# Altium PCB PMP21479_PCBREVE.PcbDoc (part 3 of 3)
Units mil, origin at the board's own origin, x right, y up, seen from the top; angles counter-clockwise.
Board outline 1915.03 x 2932.53 mil, 4 copper layers (Top Layer, Signal Layer 1, Signal Layer 2, Bottom Layer), stack 39.6 mil thick; 137 components, 82 nets, 411 pads, 91 vias.
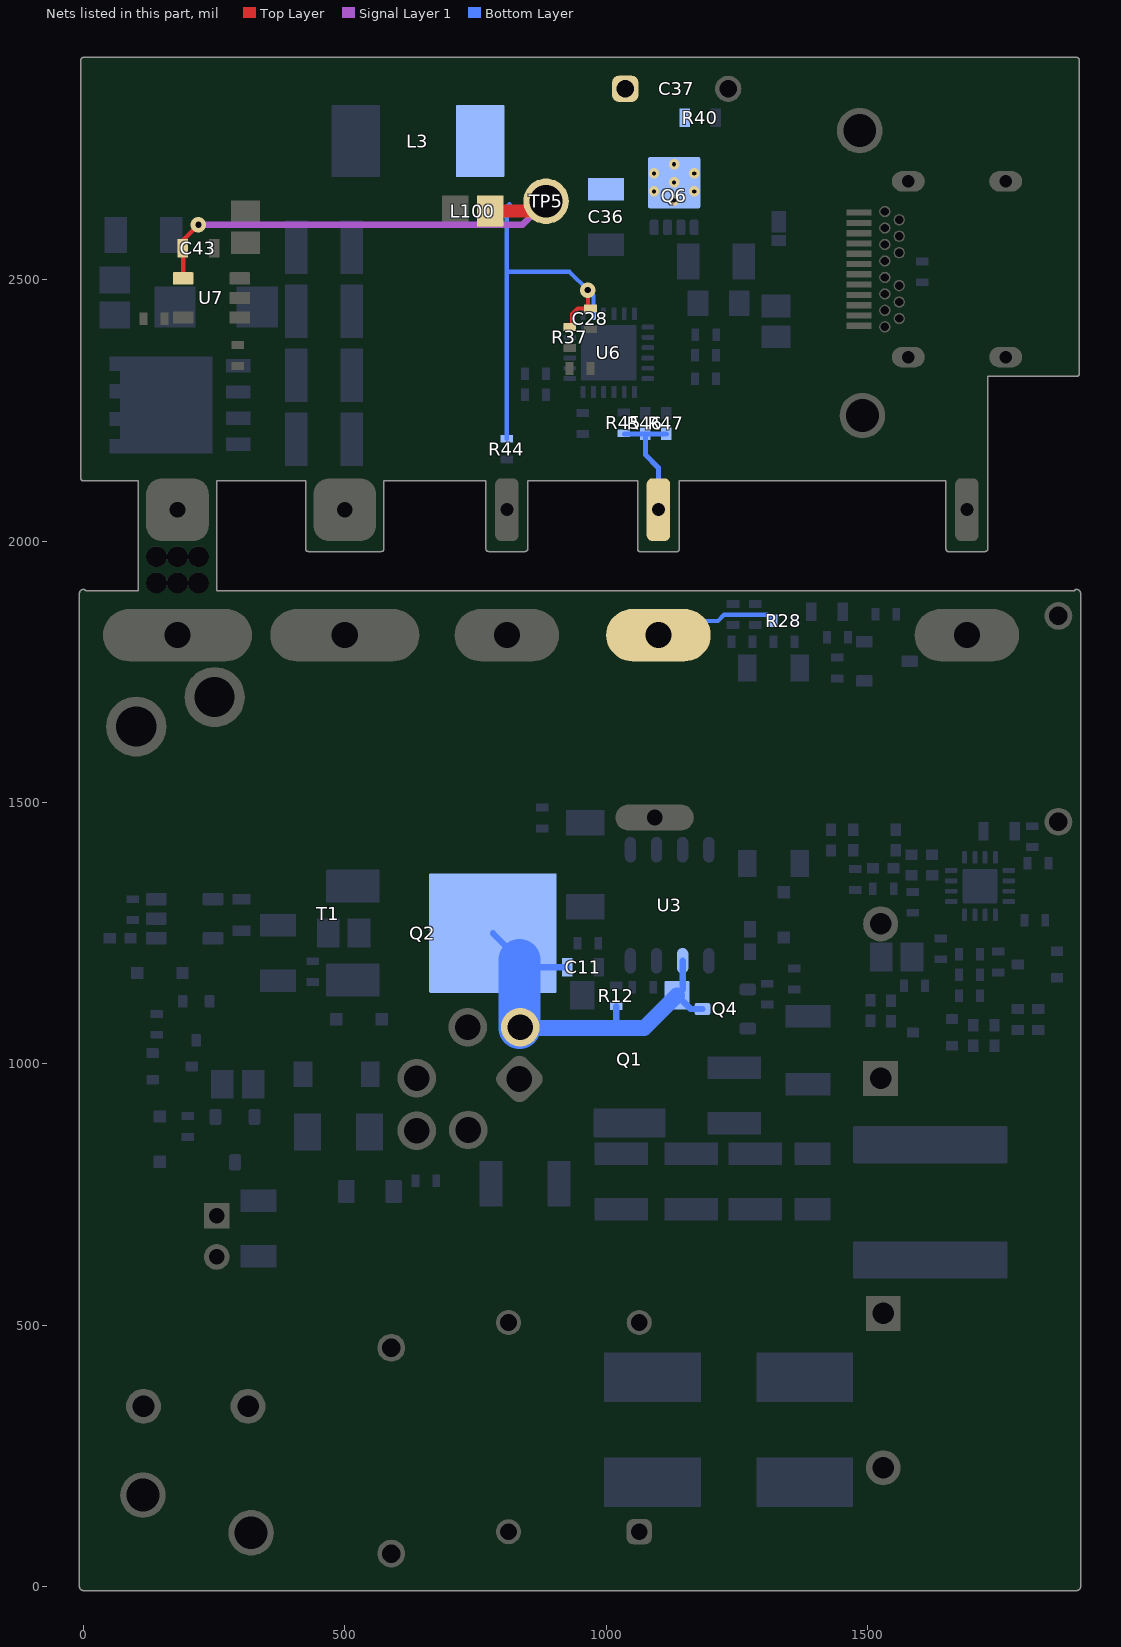
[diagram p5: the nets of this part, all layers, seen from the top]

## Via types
v1: diameter 30, hole 12, Top Layer to Bottom Layer, 44 vias
v2: diameter 30, hole 12, Top Layer to Bottom Layer, tented both sides, 31 vias
v3: diameter 19.68, hole 7.87, Top Layer to Bottom Layer, 11 vias
v4: diameter 30, hole 12, Top Layer to Bottom Layer, tented bottom, 2 vias
v5: diameter 19.68, hole 7.87, Top Layer to Bottom Layer, tented both sides, 1 vias
v6: diameter 30, hole 12, Top Layer to Bottom Layer, tented top, 1 vias
v7: diameter 34, hole 16, Top Layer to Bottom Layer, 1 vias

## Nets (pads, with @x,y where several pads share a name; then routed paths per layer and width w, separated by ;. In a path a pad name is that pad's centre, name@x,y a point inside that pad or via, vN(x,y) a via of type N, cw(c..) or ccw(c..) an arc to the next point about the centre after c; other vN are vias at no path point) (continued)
Vout: C28.1 C36.1 C37.1 C43.1 L3.2 L100.2 Q6.5 Q6.6 Q6.7 Q6.8 Q6.9@1130,2685.59 R37.2 R40.2 R44.1 TP5.1 U6.20 U7.4 | length 1680
  Top Layer w8: C43.1@190,2560 190,2575 v1(220,2605) ; U7.4@190.87,2502.4 C43.1@190.87,2559.13 ; R37.2@930.2,2409.53 935,2414.33 935,2434.41 945.59,2445 C28.1@970,2445 965,2450 v1(965,2480)
  Top Layer w25: L100.2@785,2631.14 866.14,2631.14 TP5.1@885,2650
  Signal Layer 1 w12: v1(220,2605) 840,2605 TP5.1@885,2650
  Bottom Layer w8: R44.1@810,2195 810,2515 ; 815,2645 810,2640 810,2515 ; U6.20@975.47,2434.8 975.47,2469.53 v1(965,2480) 930,2515 810,2515
  other v3: 1130,2651.65 1091.61,2668.9 1168.39,2668.9 1130,2686.14 1091.61,2703.39 1168.39,2703.39
  other v5: 1130,2720.63
VOUT_CTL: pad.2@1100,2060 R45.2 R46.1 R47.1 | length 235.4
  Bottom Layer w10: R45.2@1035,2205 R46.1@1075,2205 ; pad.2@1100,2060 1100,2140 1075,2165 R46.1@1075,2205 ; R47.1@1115,2205 R46.1@1075,2205
VOUT_CTL1: pad.0@1100,1820 R28.1 | length 241.1
  Bottom Layer w8: pad.0@1100,1820 1127.15,1847.15 1213.8,1847.15 1225.67,1859.01 1308.13,1859.01 R28.1@1320,1847.15
Vswn: C11.2 Q1.3 Q2.4 Q4.3 R12.1 T1.2 U3.6 | length 799.4
  Bottom Layer w12: Q2.4@783.36,1250 834.31,1199.05 848.56,1184.79 C11.2@925.79,1184.79 ; R12.1@1019.18,1110 1019.18,1071.68 1022.19,1068.67 ; U3.6@1146.32,1197.06 1146.32,1141.97 Q1.3@1135.55,1131.2 1161.84,1104.92 Q4.3@1184.19,1104.92
  Bottom Layer w30: T1.2@834.31,1068.67 1022.19,1068.67 1073.02,1068.67 Q1.3@1135.55,1131.2
  Bottom Layer w80: T1.2@834.31,1068.67 Q2.4@834.31,1199.05
pads on no net: J1.A2 J1.A3 J1.A8 J1.A10 J1.A11 J1.B2 J1.B3 J1.B8 J1.B10 J1.B11 Q6.9@1091.61,2706.26 Q6.9@1103.92,2651.65 Q6.9@1103.92,2686.14 Q6.9@1117.2,2706.26 Q6.9@1130,2672.89 Q6.9@1142.8,2706.26 Q6.9@1156.08,2651.65 Q6.9@1156.08,2686.14 Q6.9@1168.39,2706.26 T1.3 U2.17@1715,1340 U6.9 U6.10 U6.11 U6.25@977.64,2332.64 U6.25@977.64,2387.36 U6.25@1032.36,2332.64 U6.25@1032.36,2387.36

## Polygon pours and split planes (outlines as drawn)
NetC17_2 on Bottom Layer "BOTTOM_LAYER_NETC17_2_P006" (solid, remove dead copper, pour order 6): 75.26,1329.13 75.26,1227.57 620,1227.57 620,1329.13
Vbulk on Bottom Layer "BOTTOM_LAYER_VBULK_P000" (solid, remove dead copper, pour order 0): 1777.51,900.35 1777.51,680.39 1456.03,680.39 1456.03,900.35
no net on Bottom Layer "BOTTOM_LAYER_NONET_P044" (solid, remove dead copper, pour order 44): 1765.79,950.32
PGND on Bottom Layer "BOTTOM_LAYER_PGND_P018" (solid, remove dead copper, pour order 18): -5.02,1329.13 -5.02,560 375,560 375,1329.13
PGND on Bottom Layer "BOTTOM_LAYER_PGND_P014" (solid, remove dead copper, pour order 14): 1285,1184.09 1285,-5.02 1897.49,-5.02 1897.49,1184.09
PGND on Bottom Layer "BOTTOM_LAYER_PGND_P012" (solid, remove dead copper, pour order 12): 276.42,1470 276.42,680 1905.02,680 1905.02,1470
ICGND on Bottom Layer "BOTTOM_LAYER_ICGND_P010" (solid, remove dead copper, pour order 10): 1550,1470 1550,1017.49 1905.02,1017.49 1905.02,1470
NetC17_2 on Bottom Layer "BOTTOM_LAYER_NETC17_2_P008" (solid, remove dead copper, pour order 8): 365.51,1470.49 365.51,1270.54 1220.12,1270.54 1220.12,1470.49
Vbulk on Bottom Layer "BOTTOM_LAYER_VBULK_P004" (solid, remove dead copper, pour order 4): 1600.54,680.39 880,680.39 880,1015 1600.54,1015
SGND1 on Bottom Layer "BOTTOM_LAYER_SGND1_P022" (solid, remove dead copper, pour order 22): 1260,1900 1260,1721.57 1900,1721.57 1900,1900
VDRN on Bottom Layer "BOTTOM_LAYER_VDRN_P026" (solid, remove dead copper, pour order 26): 25,2465 25,2145 252.52,2145 252.52,2465
VN on Bottom Layer "BOTTOM_LAYER_VN_P030" (solid, remove dead copper, pour order 30): 440.32,2895 440.32,2145 790,2145 790,2895
Vout on Bottom Layer "BOTTOM_LAYER_VOUT_P028" (solid, remove dead copper, pour order 28): 705.41,2895 705.41,2625 1180,2625 1180,2895
NetQ6_1 on Bottom Layer "BOTTOM_LAYER_NETQ6_1_P034" (solid, remove dead copper, pour order 34): 1105,2615 1105,2490 1190,2490 1190,2615
VBUS on Bottom Layer "BOTTOM_LAYER_VBUS_P038" (solid, remove dead copper, pour order 38): 1230,2585 1230,2425 1570,2425 1570,2585
SGND on Bottom Layer "BOTTOM_LAYER_SGND_P040" (solid, remove dead copper, pour order 40): -5.02,2925.02 -5.02,2145 1905.02,2145 1905.02,2925.02
VDRN1 on Bottom Layer "BOTTOM_LAYER_VDRN1_P042" (solid, remove dead copper, pour order 42): 0,1895 0,1570 365,1570 365,1895
PGND on Signal Layer 2 "SIGNAL_LAYER_2_PGND_P102" (solid, remove dead copper, pour order 102): 1905.02,1469.37 515.95,1469.37 328.45,1281.87 328.45,679.37 766.42,679.37 1905.02,679.37
PGND on Signal Layer 2 "SIGNAL_LAYER_2_PGND_P068" (solid, remove dead copper, pour order 68): 0,1328.52 0,560 375,560 375,1328.52
PGND on Signal Layer 2 "SIGNAL_LAYER_2_PGND_P052" (solid, remove dead copper, pour order 52): 1285,870 1285,0 1900,0 1900,870
PGND on Signal Layer 2 "SIGNAL_LAYER_2_PGND_P048" (solid, remove dead copper, pour order 48): 553.79,1470 553.79,680.39 1880,680.39 1880,1470
ICGND on Signal Layer 2 "SIGNAL_LAYER_2_ICGND_P046" (solid, remove dead copper, pour order 46): 1488.13,1468.74 1488.13,1013.66 1900,1013.66 1900,1468.74
SGND1 on Signal Layer 2 "SIGNAL_LAYER_2_SGND1_P070" (solid, remove dead copper, pour order 70): 860,1894.5 860,1720 1900,1720 1900,1894.5
VBUS on Signal Layer 2 "SIGNAL_LAYER_2_VBUS_P078" (solid, remove dead copper, pour order 78): 1285,2865 1285,2425 1555,2425 1555,2865
SGND on Signal Layer 2 "SIGNAL_LAYER_2_SGND_P084" (solid, remove dead copper, pour order 84): 0,2920 0,2145 1900,2145 1900,2920
VDRN1 on Signal Layer 2 "SIGNAL_LAYER_2_VDRN1_P090" (solid, remove dead copper, pour order 90): 2.51,1890 2.51,1570 365,1570 365,1890
PGND on Signal Layer 1 "SIGNAL_LAYER_1_PGND_P100" (solid, remove dead copper, pour order 100): 764.72,1470.2 513.79,1470.2 326.29,1282.69 326.29,680.2 764.26,680.2 764.65,680.59
PGND on Signal Layer 1 "SIGNAL_LAYER_1_PGND_P066" (solid, remove dead copper, pour order 66): 0,1327.19 0,560 1205.94,560 1205.94,1327.19
PGND on Signal Layer 1 "SIGNAL_LAYER_1_PGND_P056" (solid, remove dead copper, pour order 56): 1285,1465 1285,0 1900,0 1900,1465
PGND on Signal Layer 1 "SIGNAL_LAYER_1_PGND_P050" (solid, remove dead copper, pour order 50): 520.5,1470 520.5,680 1880,680 1880,1470
SGND1 on Signal Layer 1 "SIGNAL_LAYER_1_SGND1_P072" (solid, remove dead copper, pour order 72): 860,1894.5 860,1720 1900,1720 1900,1894.5
SGND on Signal Layer 1 "SIGNAL_LAYER_1_SGND_P080" (solid, remove dead copper, pour order 80): 0,2920 0,2145 1900,2145 1900,2920
VN1 on Signal Layer 1 "SIGNAL_LAYER_1_VN1_P092" (solid, remove dead copper, pour order 92): 2.51,1890.46 2.52,1560 700,1560 700,1890.46
PGND on Top Layer "TOP_LAYER_PGND_P096" (solid, remove dead copper, pour order 96): 767.41,1470 516.48,1470 328.98,1282.5 328.98,680 766.95,680 767.34,680.39
PGND on Top Layer "TOP_LAYER_PGND_P064" (solid, remove dead copper, pour order 64): 0,1328.52 0,560 375,560 375,1328.52
PGND on Top Layer "TOP_LAYER_PGND_P062" (solid, remove dead copper, pour order 62): 1285,1470 1285,0 1900,0 1900,1470
PGND on Top Layer "TOP_LAYER_PGND_P058" (solid, remove dead copper, pour order 58): 525.21,1470 525.21,680 1880,680 1880,1470
SGND1 on Top Layer "TOP_LAYER_SGND1_P074" (solid, remove dead copper, pour order 74): 860,1895 860,1720 1900,1720 1900,1895
VBUS on Top Layer "TOP_LAYER_VBUS_P076" (solid, remove dead copper, pour order 76): 1286.9,2585 1286.9,2425 1545,2425 1545,2585
SGND on Top Layer "TOP_LAYER_SGND_P086" (solid, remove dead copper, pour order 86): 0,2920 0,2145 1900,2145 1900,2920
VN1 on Top Layer "TOP_LAYER_VN1_P094" (solid, remove dead copper, pour order 94): 0,1890 0,1565 700,1565 700,1890

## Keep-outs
Keep-Out Layer:
  text ".Layer_Name" at 577,-858.49 h60

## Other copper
Top Layer:
  text ".Layer_Name" at 577,-858.49 h60
Signal Layer 1:
  pour cut-out: 655,1370 655,1115 1005.12,1115 1005.12,1370
  pour cut-out: 803.31,1275 803.31,1040.65 1168.81,1040.65 1168.81,1275
Signal Layer 2:
  pour cut-out: 802.84,1275.2 802.84,1040.65 1169.05,1040.65 1169.05,1275.2
  pour cut-out: 655,1370.01 655,1115 1005,1115 1005,1370.01
Bottom Layer:
  text ".Layer_Name" at 577,-858.49 h60

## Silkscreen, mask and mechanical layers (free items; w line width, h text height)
Top Overlay:
  text "NEUT" at 235,190 h40
  text "LINE" at 40,50 h40
  text ".Layer_Name" at 577,-858.49 h60
Bottom Overlay:
  text "PMP21479PCB-E" at 1870,40 h108.27
  text ".Layer_Name" at 577,-858.49 h60
Top Paste:
  text ".Layer_Name" at 577,-858.49 h60
Bottom Paste:
  text ".Layer_Name" at 577,-858.49 h60
Top Solder:
  text ".Layer_Name" at 577,-858.49 h60
  text ".Layer_Name" at 577,-858.49 h60
Bottom Solder:
  text ".Layer_Name" at 577,-858.49 h60
Drill Guide:
  text ".Layer_Name" at 577,-858.49 h60
M1 Board Outline:
  lines w5: 285,1567.5 ccw(c285,1570) 286.77,1568.23 ; 285,1567.5 ccw(c285,1570) 286.77,1568.23 ; 285,1567.5 27.5,1567.5 27.5,1532.15 299.31,1532.15 418.58,1651.42 ; 286.77,1568.23 406.04,1687.5 997.5,1687.5 997.5,1652.15 420.35,1652.15 ; 400,482.5 ccw(c400,485) 402.5,485 ; 400,482.5 ccw(c400,485) 402.5,485 ; 400,482.5 47.5,482.5 47.5,447.5 437.5,447.5 437.5,620 ; 402.5,485 402.5,657.5 1247.5,657.5 1247.5,622.5 440,622.5 ; 418.58,1651.42 cw(c420.35,1649.65) 420.35,1652.15 ; 418.58,1651.42 cw(c420.35,1649.65) 420.35,1652.15 ; 437.5,620 cw(c440,620) 440,622.5 ; 437.5,620 cw(c440,620) 440,622.5 ; -10.02,0 ccw(c0,0) 0,-10.02 1900,-10.02 ccw(c1900,0) 1910.02,0 1910.02,1900 ccw(c1900,1900) 1900,1910.02 ccw(c1900,1902.5) 1894.4,1907.52 257.52,1907.52 257.52,2112.49 422.48,2112.72 422.48,1985 ccw(c430,1985) 430,1977.48 570,1977.48 ccw(c570,1985) 577.52,1985 577.52,2112.48 767.48,2112.48 767.48,1985 ccw(c775,1985) 775,1977.48 845,1977.48 ccw(c845,1985) 852.52,1985 852.52,2112.48 1057.48,2112.48 1057.48,1984.76 ccw(c1065,1984.76) 1065,1977.24 1135,1977.24 ccw(c1135,1984.76) 1142.52,1984.76 1142.52,2112.72 1647.48,2112.49 1647.48,1984.76 ccw(c1655,1984.76) 1656.9,1977.48 1725,1977.48 ccw(c1725,1985) 1732.52,1985 1732.52,2312.48 1900,2312.48 ccw(c1900,2320) 1907.52,2320 1907.52,2920 ccw(c1900,2920) 1900,2927.52 0,2927.52 ccw(c0,2920) -7.52,2920 -7.52,2120 ccw(c0,2120) 0,2112.48 102.48,2112.48 102.48,1907.52 5.6,1907.52 ccw(c0,1902.5) 0,1910.02 ccw(c0,1900) -10.02,1900 -10.02,0
  text ".Layer_Name" at 577,-858.49 h60
M2 Board Dimensions:
  rectangle: 125,-400 500,-275
  rectangle: 0,-275 125,-150
  lines w7: 0,-275 1000,-275 ; 125,-400 125,-150 ; 250,-400 250,-150 ; 500,-400 500,-150 ; 750,-400 750,-150 ; 0,-400 0,-150 1000,-150 1000,-400 0,-400
  text ".Layer_Name" at 577,-858.49 h60
M3 3D STEP Top:
  text ".Layer_Name" at 577,-858.49 h60
M4 3D STEP Bottom:
  text ".Layer_Name" at 577,-858.49 h60
M5 Assembly Top:
  lines w10: -292,-930.17 6308,-930.17 ; -292,-726.83 6310,-726.83 ; -292,-523.5 -292,-1133.5 3713,-1133.5 6310,-1133.5 6310,-523.5 -291.5,-523.5 -291.5,-1133.5 1284,-1133.5 ; 2173,-1133.5 2173,-523.5 ; 3440,-726.83 3440,-523.5 ; 4280,-726.83 4280,-523.5 ; 4902,-1140 4902,-937.17
  text "COMPONENTS MARKED 'DNP' SHOULD NOT BE POPULATED." at 1153.5,-318.5 h60
  text "ASSEMBLY VARIANT:" at 1153,-434 h60
  text ".VariantName" at 2189,-434 h60
  text "PCB VIEWED FROM TOP SIDE" at -228.5,-655.67 h60
  text "BOARD #:" at 2248,-655.67 h60
  text ".PRJ_Number" at 2793.5,-655.67 h60
  text "REV:" at 3638,-655.67 h60
  text ".PCB_Rev" at 3929.5,-655.67 h60
  text "SVN REV:" at 4476,-655.67 h60
  text ".VersionControl_RevNumber" at 4982,-655.67 h60
  text "TID #:" at 2248,-859 h60
  text ".TID" at 2793.5,-859 h60
  text "PLOT NAME =" at -228.5,-1064.34 h60
  text ".plot_File_Name" at 577,-1064.34 h60
  text "GENERATED    :" at 2250,-1064.34 h60
  text ".Print_Date" at 3119.5,-1064.34 h60
  text ".Print_Time" at 3848.5,-1064.34 h60
  text "TEXAS INSTRUMENTS" at 5113,-1064.34 h60
M6 Assembly Bottom:
  lines w10: -292.5,-727.33 6309.5,-727.33 ; -290.5,-930.67 6309.5,-930.67 ; 1115.5,-1140.5 1115.5,-937.67 ; 1737.5,-727.33 1737.5,-524 ; 2577.5,-727.33 2577.5,-524 ; 3844.5,-1134 3844.5,-524 ; 4733.5,-1134 6309,-1134 6309,-524 -292.5,-524 -292.5,-1134 2304.5,-1134 6309.5,-1134 6309.5,-524
  text "COMPONENTS MARKED 'DNP' SHOULD NOT BE POPULATED." at 6102,-318 h60
  text ".VariantName" at 5058,-434 h60
  text "ASSEMBLY VARIANT:" at 6097,-434 h60
  text ".VersionControl_RevNumber" at 1035.5,-656.17 h60
  text "SVN REV:" at 1541.5,-656.17 h60
  text ".PCB_Rev" at 2088,-656.17 h60
  text "REV:" at 2379.5,-656.17 h60
  text ".PRJ_Number" at 3224,-656.17 h60
  text "BOARD #:" at 3769.5,-656.17 h60
  text "PCB VIEWED FROM BOTTOM SIDE" at 6246,-656.17 h60
  text ".TID" at 3224,-859.5 h60
  text "TID #:" at 3769.5,-859.5 h60
  text "TEXAS INSTRUMENTS" at 904.5,-1064.84 h60
  text ".Print_Time" at 2169,-1064.84 h60
  text ".Print_Date" at 2898,-1064.84 h60
  text "GENERATED    :" at 3767.5,-1064.84 h60
  text ".plot_File_Name" at 5440.5,-1064.84 h60
  text "PLOT NAME =" at 6246,-1064.84 h60
M9 Title Sheet:
  drawing of 57 lines, arcs and shapes, not listed
  text "1" at 739.84,8036.5 h70
  text "2" at 3235.5,8036.5 h70
  text "3" at 5724.84,8036.5 h70
  text "4" at 8231.51,8036.5 h70
  text "5" at 10730.5,8036.5 h70
  text "6" at 13235.5,8036.5 h70
  text "A" at -416.5,6893.5 h70
  text "A" at 14383.5,6893.5 h70
  text "B" at -416.5,4513.5 h70
  text "B" at 14383.5,4513.5 h70
  text "C" at -416.5,2138.5 h70
  text "C" at 14383.5,2138.5 h70
  text "PROJECT TITLE:" at 11343.5,277.5 h45
  text ".PRJ_Title" at 11393.5,144.17 h70
  text "DESIGNED FOR:" at 11343.5,-23.5 h45
  text ".PRJ_Customer" at 11393.5,-163.5 h70
  text "D" at -416.5,-231.5 h70
  text "D" at 14383.5,-231.5 h70
  text "FILE NAME:" at 11343.5,-323.5 h45
  text ".PCB_File_Name_No_Path" at 11393.5,-443.5 h70
  text "Texas Instruments (TI) and/or its licensors do not warrant the accuracy or completeness of this specification" at 6374,-605.34 h45
  text "ENGINEER:" at 11343.5,-613.5 h45
  text "LAYOUT BY:" at 12848.5,-613.5 h45
  text "or any information contained therein. TI and/or its licensors do not warrant that this design will meet" at 6329.01,-718 h45
  text ".PRJ_Engineer" at 11393.5,-768.49 h70
  text ".PCB_Layout" at 12899,-768.49 h70
  text "the specifications, will be suitable for your application or fit for any particular purpose, or will operate in" at 6329.01,-830.67 h45
  text ".Layer_Name" at 577,-858.49 h60
  text "ALTIUM DESIGNER VERSION:" at 12848.5,-923.5 h45
  text "an implementation. TI and/or its licensors do not warrant that the design is production worthy. You should" at 6329.01,-943.33 h45
  text "completely validate and test your design implementation to confirm the system functionality for your application." at 6374,-1056 h45
  text ".print_Scale" at 11393.5,-1056.83 h70
  text ".Application_BuildNumber" at 12899,-1056.83 h70
  text "1" at 739.84,-1263.5 h70
  text "2" at 3235.5,-1263.5 h70
  text "3" at 5724.84,-1263.5 h70
  text "4" at 8231.51,-1263.5 h70
  text "5" at 10730.5,-1263.5 h70
  text "6" at 13235.5,-1263.5 h70
M10 Fab Notes:
  drawing of 189 lines, arcs and shapes, not listed
  text "DESIGN INFORMATION" at 12382.02,6356.17 h60
  text "MIN. TRACK WIDTH:" at 11737.46,6224.05 h60
  text "8" at 12833.7,6224.05 h60
  text "MIL" at 12988.46,6224.05 h60
  text "MIN. CLEARANCE:" at 11737.46,6099.92 h60
  text "0.2" at 12773.7,6099.93 h60
  text "mm" at 12988.46,6099.92 h60
  text "MIN. VIA PAD SIZE:" at 11737.46,5975.8 h60
  text "24" at 12803.71,5975.8 h60
  text "MIL" at 12988.46,5975.8 h60
  text "0.05mm (2MIL)" at 12432.46,5845.9 h60
  text "MINIMUM ANNULAR RING" at 11408.23,5837.67 h60
  text "EXTERNAL" at 13140.46,5837.67 h60
  text "PER" at 11608.23,5727.55 h60
  text "IPC-D-275 CLASS 2 LEVEL C" at 11828.23,5727.54 h60
  text "MIL, HOLES" at 13316.46,5627.07 h60
  text "+/-" at 12924,5618.48 h60
  text "+/-" at 13778,5618.48 h60
  text "REGISTRATION TOLERANCES:" at 11408.23,5617.42 h60
  text "METAL" at 12608,5617.42 h60
  text "5" at 13184.2,5617.42 h60
  text "3" at 14017.2,5617.42 h60
  text "MIL" at 14133.46,5617.42 h60
  text "HOLE SIZE TOLERANCE (UNLESS OTHERWISE SPECIFIED):" at 11408.23,5519.1 h60
  text "+/-" at 13778,5516.23 h60
  text "3" at 14017.2,5515.17 h60
  text "MIL" at 14133.46,5515.17 h60
  text "MATERIAL:" at 11333.46,5377.52 h60
  text "FR-4 High Tg" at 12319.9,5249 h60
  text "X" at 12175.46,5241.01 h60
  text "FR-408" at 11754.46,5236.49 h60
  text "OTHER" at 13242.46,5236.49 h60
  text "62 MIL (1.6mm) +/-10%" at 12074.56,5093.46 h60
  text "X" at 13240,5088 h60
  text "40MIL" at 13725,5086 h72
  text "THICKNESS:" at 11408.23,5085.24 h60
  text "OTHER" at 13359.46,5085.24 h60
  text "TOLERANCE:" at 11408.23,4946.92 h60
  text "X" at 12256.46,4946.92 h60
  text "ANSI IPC-6012 TYPE 3 CLASS 2" at 12434.48,4946.92 h60
  text "OTHER +/-" at 12434.46,4802.73 h60
  text "BOW & TWIST:" at 11408.23,4657.54 h60
  text "X" at 12256.46,4657.54 h60
  text "ANSI IPC-6012 TYPE 3 CLASS 2" at 12434.48,4657.54 h60
  text "OTHER +/-" at 12434.46,4510.85 h60
  text "DRILLING:" at 11333.46,4380.23 h60
  text "NC_DRILL FILES" at 13094.46,4275.04 h60
  text "REFERENCE:" at 11408.23,4271.1 h60
  text "X" at 12065.46,4271.01 h60
  text "AS SHOWN" at 12243.46,4271.1 h60
  text "X" at 12966.46,4271.1 h60
  text "OTHER" at 13392.46,4128.85 h60
  text "PTH COPPER THICKNESS:" at 11407.91,4125.32 h60
  text "X" at 12547.14,4125.32 h60
  text "20-30 um" at 12675.14,4125.32 h60
  text "BOARD FINISH:" at 11333.46,3977.73 h60
  text "SILKSCREEN:" at 11488.68,3867.6 h60
  text "X" at 12446.46,3867.6 h60
  text "TOP" at 12563.46,3867.6 h60
  text "X" at 12956.46,3867.6 h60
  text "BOTTOM" at 13074.46,3867.6 h60
  text "SILKSCREEN COLOR:" at 11488.68,3712.41 h60
  text "X" at 12445.46,3712.41 h60
  text "WHITE" at 12563.46,3712.41 h60
  text "OTHER" at 13074.46,3712.41 h60
  text "X" at 12576.46,3568.96 h60
  text "GREEN" at 12694.46,3568.96 h60
  text "OTHER" at 13312.46,3568.96 h60
  text "SOLDER RESIST COLOR:" at 11488.68,3562.1 h60
  text "X" at 12576.46,3414.71 h60
  text "MATTE" at 12694.46,3414.71 h60
  text "SEMI-GLOSS" at 13312,3414.07 h60
  text "IMMERSION GOLD (ENIG)" at 12394.46,3241.94 h60
  text "ENEPIG" at 13732,3234.72 h60
  text "SURFACE FINISH:" at 11333.46,3233.72 h60
  text "X" at 12216.46,3233.72 h60
  text "IMM. TIN/SILVER OR EQUIV" at 11663,3096.4 h60
  text "OTHER" at 13094.46,3092.47 h60
  text "ARRAY/PANEL:" at 11333.46,2937.09 h60
  text "CUT AND TRIM PER M1 BOARD OUTLINE" at 12394.46,2928.87 h60
  text "N.C. ROUTE" at 12394.46,2792.9 h60
  text "X" at 13082.46,2792.9 h60
  text "V. SCORE" at 13260.46,2792.9 h60
  text "CERTIFICATION:" at 11333.46,2663.77 h60
  text "MATERIALS AND WORKMANSHIP FOR ALL PCBS" at 12058.46,2663.77 h60
  text "TO MEET OR EXCEED THE REQUIREMENTS OF:" at 12058.46,2569.71 h60
  text "X" at 11695.97,2441.08 h60
  text "ANSI IPC-A-600F CLASS ->" at 11823.96,2441.08 h60
  text "X" at 13471.97,2441.08 h60
  text "2" at 13581.96,2441.08 h60
  text "1" at 13266.96,2439.58 h60
  text "3" at 13935.96,2439.58 h60
  text "X" at 12507.97,2293.39 h60
  text "RoHS" at 12635.96,2293.39 h60
  text "OTHER" at 13280.36,2293.39 h60
  text "PER ORDER" at 13677.42,2293.39 h60
  text "ALL BOARDS MUST MEET OR EXCEED UL94-V0 REQUIREMENTS." at 11361,2139.57 h60
  text "PCB MUST BEAR THE UL94V-0 UL REGISTERED MATERIAL ID NUMBER" at 11361,2023.5 h60
  text "ADDITIONAL REQUIREMENTS:" at 11333.46,1854.08 h60
  text "MICROSECTION:" at 11408.23,1746.95 h60
  text "YES" at 12313.96,1746.95 h60
  text "REQUIRED" at 13175.46,1602.62 h60
  text "BARE BOARD ELEC. TEST:" at 11408.23,1599.76 h60
  text "NONE" at 12713.96,1599.76 h60
  text "X" at 13057.46,1599.76 h60
  text "PER ORDER" at 13767.46,1599.76 h60
  text "XX MIL VIAS REQUIRE NON-CONDUCTIVE FILL AND PLANARIZE" at 11576.38,1394.82 h59
  text "XX MIL VIAS REQUIRE CONDUCTIVE FILL AND PLANARIZE" at 11584.38,1290.84 h60
  text "OUTER XX MIL VIAS REQUIRE 50 OHM SINGLE-ENDED IMPEDANCE" at 11583.39,1127.46 h58
  text "LAYER 2 & 3 (INNER LAYERS) XX MIL WIDE, XX MIL SPACE / TRACES REQUIRE 100 OHM DIFFERENTIAL IMPEDANCE" at 11575.39,891.74 h60
  text ".Layer_Name" at 577,-858.49 h60
M11 Gerber Information:
  lines w10: -292,-930.17 6308,-930.17 ; -292,-726.83 6310,-726.83 ; -292,-523.5 -292,-1133.5 3713,-1133.5 6310,-1133.5 6310,-523.5 -291.5,-523.5 -291.5,-1133.5 1284,-1133.5 ; 2173,-1133.5 2173,-523.5 ; 3440,-726.83 3440,-523.5 ; 4280,-726.83 4280,-523.5 ; 4902,-1140 4902,-937.17
  text "ALL ARTWORK VIEWED FROM TOP SIDE" at -228.5,-655.67 h60
  text "BOARD #:" at 2248,-655.67 h60
  text ".PRJ_Number" at 2793.5,-655.67 h60
  text "REV:" at 3638,-655.67 h60
  text ".PCB_Rev" at 3929.5,-655.67 h60
  text "SVN REV:" at 4476,-655.67 h60
  text ".VersionControl_RevNumber" at 4982,-655.67 h60
  text "LAYER NAME =" at -228.5,-858.49 h60
  text "TID #:" at 2248,-859 h60
  text ".TID" at 2793.5,-859 h60
  text "PLOT NAME =" at -228.5,-1064.34 h60
  text ".plot_File_Name" at 577,-1064.34 h60
  text "GENERATED    :" at 2250,-1064.34 h60
  text ".Print_Date" at 3119.5,-1064.34 h60
  text ".Print_Time" at 3848.5,-1064.34 h60
  text "TEXAS INSTRUMENTS" at 5113,-1064.34 h60
M12 Stackup:
  drawing of 295 lines, arcs and shapes, not listed
  text "Layer" at 9803.74,7856 h60
  text "Name" at 10213.66,7856 h60
  text "Material" at 11153.4,7856 h60
  text "Thickness" at 12013.16,7856 h60
  text "Constant" at 12663,7856 h60
  text "Board Layer Stack" at 13232.86,7856 h60
  text "1" at 9803.74,7736 h60
  text "Top Overlay" at 10213.66,7736 h60
  text "2" at 9803.74,7616 h60
  text "Top Solder" at 10213.66,7616 h60
  text "Solder Resist" at 11153.4,7616 h60
  text "0.40mil" at 12013.16,7616 h60
  text "3.5" at 12663,7616 h60
  text "3" at 9803.74,7496 h60
  text "Top Layer" at 10213.66,7496 h60
  text "Copper" at 11153.4,7496 h60
  text "1.40mil" at 12013.16,7496 h60
  text "4" at 9803.74,7376 h60
  text "Dielectric 1" at 10213.66,7376 h60
  text "FR-4" at 11153.4,7376 h60
  text "8.00mil" at 12013.16,7376 h60
  text "4.2" at 12663,7376 h60
  text "5" at 9803.74,7256 h60
  text "Signal Layer 1" at 10213.66,7256 h60
  text "Copper" at 11153.4,7256 h60
  text "1.40mil" at 12013.16,7256 h60
  text "6" at 9803.74,7136 h60
  text "Dielectric 2" at 10213.66,7136 h60
  text "FR-4" at 11153.4,7136 h60
  text "18.00mil" at 12013.16,7136 h60
  text "4.2" at 12663,7136 h60
  text "7" at 9803.74,7016 h60
  text "Signal Layer 2" at 10213.66,7016 h60
  text "Copper" at 11153.4,7016 h60
  text "1.40mil" at 12013.16,7016 h60
  text "8" at 9803.74,6896 h60
  text "Dielectric 3" at 10213.66,6896 h60
  text "FR-4" at 11153.4,6896 h60
  text "8.00mil" at 12013.16,6896 h60
  text "4.2" at 12663,6896 h60
  text "9" at 9803.74,6776 h60
  text "Bottom Layer" at 10213.66,6776 h60
  text "Copper" at 11153.4,6776 h60
  text "1.40mil" at 12013.16,6776 h60
  text "10" at 9803.74,6656 h60
  text "Bottom Solder" at 10213.66,6656 h60
  text "Solder Resist" at 11153.4,6656 h60
  text "0.40mil" at 12013.16,6656 h60
  text "3.5" at 12663,6656 h60
  text "11" at 9803.74,6536 h60
  text "Bottom Overlay" at 10213.66,6536 h60
  text ".Layer_Name" at 577,-858.49 h60
M13 Component Bodies Top:
  text ".Layer_Name" at 577,-858.49 h60
M14 Component Bodies Bottom:
  text ".Layer_Name" at 577,-858.49 h60
M15 Courtyards Top:
  text ".Layer_Name" at 577,-858.49 h60
M16 Courtyards Bottom:
  text ".Layer_Name" at 577,-858.49 h60
Drill Drawing:
  circle w10: c5363.72,2073.69 r16.58
  circle w10: c5363.72,2073.69 r27.63
  circle w10: c5363.72,1079.13 r27.63
  lines w10: 5336.09,1300.15 5391.34,1300.15 5391.34,1355.4 5336.09,1355.4 5336.09,1300.15 ; 5336.09,1479.72 5391.34,1479.72 5363.72,1424.47 5336.09,1479.72 ; 5336.09,1686.92 5349.9,1686.92 5349.9,1673.11 5377.53,1673.11 5377.53,1686.92 5391.34,1686.92 5391.34,1714.55 5377.53,1714.55 5377.53,1728.36 5349.9,1728.36 5349.9,1714.55 5336.09,1714.55 5336.09,1686.92 ; 5336.09,1797.43 5391.34,1797.43 5391.34,1852.68 5336.09,1852.68 5336.09,1797.43 ; 5336.09,2198.01 5363.72,2170.39 5391.34,2198.01 5363.72,2225.64 5336.09,2198.01 ; 5336.09,2294.71 5336.09,2308.52 5349.9,2322.33 5336.09,2336.15 5336.09,2349.96 5349.9,2349.96 5363.72,2336.15 5377.53,2349.96 5391.34,2349.96 5391.34,2336.15 5377.53,2322.33 5391.34,2308.52 5391.34,2294.71 5377.53,2294.71 5363.72,2308.52 5349.9,2294.71 5336.09,2294.71 ; 5336.09,2805.8 5349.9,2805.8 5349.9,2791.99 5377.53,2791.99 5377.53,2805.8 5391.34,2805.8 5391.34,2833.43 5377.53,2833.43 5377.53,2847.24 5349.9,2847.24 5349.9,2833.43 5336.09,2833.43 5336.09,2805.8 ; 5336.09,2930.12 5349.9,2930.12 5363.72,2916.31 5377.53,2930.12 5391.34,2930.12 5377.53,2943.93 5391.34,2957.75 5377.53,2957.75 5363.72,2971.56 5349.9,2957.75 5336.09,2957.75 5349.9,2943.93 5336.09,2930.12 ; 5336.09,3040.63 5363.72,3054.44 5391.34,3040.63 5377.53,3068.25 5391.34,3095.88 5363.72,3082.07 5336.09,3095.88 5349.9,3068.25 5336.09,3040.63 ; 5336.09,3164.95 5363.72,3178.76 5391.34,3164.95 5377.53,3192.57 5391.34,3220.2 5363.72,3206.39 5336.09,3220.2 5349.9,3192.57 5336.09,3164.95 ; 5336.09,3344.52 5391.34,3344.52 5363.72,3289.27 5336.09,3344.52 ; 5347.14,1808.48 5380.29,1808.48 5380.29,1841.63 5347.14,1841.63 5347.14,1808.48 ; 5347.14,2305.76 5347.14,2314.04 5355.43,2322.33 5347.14,2330.62 5347.14,2338.91 5355.43,2338.91 5363.72,2330.62 5372.01,2338.91 5380.29,2338.91 5380.29,2330.62 5372.01,2322.33 5380.29,2314.04 5380.29,2305.76 5372.01,2305.76 5363.72,2314.04 5355.43,2305.76 5347.14,2305.76 ; 5347.14,2811.32 5355.43,2811.32 5355.43,2803.04 5372.01,2803.04 5372.01,2811.32 5380.29,2811.32 5380.29,2827.9 5372.01,2827.9 5372.01,2836.19 5355.43,2836.19 5355.43,2827.9 5347.14,2827.9 5347.14,2811.32 ; 5347.14,3051.68 5363.72,3059.96 5380.29,3051.68 5372.01,3068.25 5380.29,3084.83 5363.72,3076.54 5347.14,3084.83 5355.43,3068.25 5347.14,3051.68 ; 5347.14,3333.47 5380.29,3333.47 5363.72,3300.32 5347.14,3333.47
  lines w12: 5286,1014.21 8517.49,1014.21 ; 5286,3376.29 8517.49,3376.29 ; 5623.86,889.89 5623.86,3500.61 ; 5955.86,889.89 5955.86,3500.61 ; 6592.43,889.89 6592.43,3500.61 ; 6851.57,889.89 6851.57,3500.61 ; 7226.72,889.89 7226.72,3500.61 ; 7951.05,889.89 7951.05,3500.61 ; 5286,889.89 8517.49,889.89 8517.49,3500.61 5286,3500.61 5286,889.89
  text "Symbol" at 5360.59,3413.59 h72
  text "Quantity" at 5661.16,3413.59 h72
  text "Finished Hole Size" at 5993.16,3413.59 h72
  text "Plated" at 6629.72,3413.59 h72
  text "Hole Type" at 6888.86,3413.59 h72
  text "Drill Layer Pair" at 7264.02,3413.59 h72
  text "Hole Tolerance" at 7988.35,3413.59 h72
  text "6" at 5661.16,3289.27 h60
  text "40.00mil (1.016mm)" at 5993.16,3289.27 h60
  text "NPTH" at 6629.72,3289.27 h60
  text "Round" at 6888.86,3289.27 h60
  text "Top Layer - Bottom Layer" at 7264.02,3289.27 h60
  text "12" at 5661.16,3164.95 h60
  text "7.87mil (0.200mm)" at 5993.16,3164.95 h60
  text "PTH" at 6629.72,3164.95 h60
  text "Round" at 6888.86,3164.95 h60
  text "Top Layer - Bottom Layer" at 7264.02,3164.95 h60
  text "78" at 5661.16,3040.63 h60
  text "12.00mil (0.305mm)" at 5993.16,3040.63 h60
  text "PTH" at 6629.72,3040.63 h60
  text "Round" at 6888.86,3040.63 h60
  text "Top Layer - Bottom Layer" at 7264.02,3040.63 h60
  text "14" at 5661.16,2916.31 h60
  text "15.75mil (0.400mm)" at 5993.16,2916.31 h60
  text "PTH" at 6629.72,2916.31 h60
  text "Round" at 6888.86,2916.31 h60
  text "Top Layer - Bottom Layer" at 7264.02,2916.31 h60
  text "1" at 5661.16,2791.99 h60
  text "16.00mil (0.406mm)" at 5993.16,2791.99 h60
  text "PTH" at 6629.72,2791.99 h60
  text "Round" at 6888.86,2791.99 h60
  text "Top Layer - Bottom Layer" at 7264.02,2791.99 h60
  text "3" at 5661.16,2667.67 h60
  text "25.00mil (0.635mm)" at 5993.16,2667.67 h60
  text "PTH" at 6629.72,2667.67 h60
  text "Round" at 6888.86,2667.67 h60
  text "Top Layer - Bottom Layer" at 7264.02,2667.67 h60
  text "H" at 5335.31,2657.68 h55.25
  text "2" at 5661.16,2543.35 h60
  text "29.53mil (0.750mm)" at 5993.16,2543.35 h60
  text "PTH" at 6629.72,2543.35 h60
  text "Round" at 6888.86,2543.35 h60
  text "Top Layer - Bottom Layer" at 7264.02,2543.35 h60
  text "D" at 5335.31,2533.36 h55.25
  text "2" at 5661.16,2419.03 h60
  text "30.00mil (0.762mm)" at 5993.16,2419.03 h60
  text "PTH" at 6629.72,2419.03 h60
  text "Round" at 6888.86,2419.03 h60
  text "Top Layer - Bottom Layer" at 7264.02,2419.03 h60
  text "F" at 5335.31,2409.03 h55.25
  text "4" at 5661.16,2294.71 h60
  text "32.00mil (0.813mm)" at 5993.16,2294.71 h60
  text "PTH" at 6629.72,2294.71 h60
  text "Round" at 6888.86,2294.71 h60
  text "Top Layer - Bottom Layer" at 7264.02,2294.71 h60
  text "2" at 5661.16,2170.39 h60
  text "33.47mil (0.850mm)" at 5993.16,2170.39 h60
  text "PTH" at 6629.72,2170.39 h60
  text "Round" at 6888.86,2170.39 h60
  text "Top Layer - Bottom Layer" at 7264.02,2170.39 h60
  text "4" at 5661.16,2046.07 h60
  text "35.43mil (0.900mm)" at 5993.16,2046.07 h60
  text "PTH" at 6629.72,2046.07 h60
  text "Round" at 6888.86,2046.07 h60
  text "Top Layer - Bottom Layer" at 7264.02,2046.07 h60
  text "6" at 5661.16,1921.75 h60
  text "41.34mil (1.050mm)" at 5993.16,1921.75 h60
  text "PTH" at 6629.72,1921.75 h60
  text "Round" at 6888.86,1921.75 h60
  text "Top Layer - Bottom Layer" at 7264.02,1921.75 h60
  text "A" at 5335.31,1911.76 h55.25
  text "6" at 5661.16,1797.43 h60
  text "49.21mil (1.250mm)" at 5993.16,1797.43 h60
  text "PTH" at 6629.72,1797.43 h60
  text "Round" at 6888.86,1797.43 h60
  text "Top Layer - Bottom Layer" at 7264.02,1797.43 h60
  text "5" at 5661.16,1673.11 h60
  text "63.00mil (1.600mm)" at 5993.16,1673.11 h60
  text "PTH" at 6629.72,1673.11 h60
  text "Round" at 6888.86,1673.11 h60
  text "Top Layer - Bottom Layer" at 7264.02,1673.11 h60
  text "2" at 5661.16,1548.79 h60
  text "76.77mil (1.950mm)" at 5993.16,1548.79 h60
  text "PTH" at 6629.72,1548.79 h60
  text "Round" at 6888.86,1548.79 h60
  text "Top Layer - Bottom Layer" at 7264.02,1548.79 h60
  text "C" at 5335.31,1538.8 h55.25
  text "4" at 5661.16,1424.47 h60
  text "23.62mil (0.600mm)" at 5993.16,1424.47 h60
  text "PTH" at 6629.72,1424.47 h60
  text "Slot" at 6888.86,1424.47 h60
  text "Top Layer - Bottom Layer" at 7264.02,1424.47 h60
  text "1" at 5661.16,1300.15 h60
  text "30.00mil (0.762mm)" at 5993.16,1300.15 h60
  text "PTH" at 6629.72,1300.15 h60
  text "Slot" at 6888.86,1300.15 h60
  text "Top Layer - Bottom Layer" at 7264.02,1300.15 h60
  text "3" at 5661.16,1175.83 h60
  text "50.00mil (1.270mm)" at 5993.16,1175.83 h60
  text "PTH" at 6629.72,1175.83 h60
  text "Slot" at 6888.86,1175.83 h60
  text "Top Layer - Bottom Layer" at 7264.02,1175.83 h60
  text "E" at 5335.31,1165.84 h55.25
  text "2" at 5661.16,1051.51 h60
  text "50.00mil (1.270mm)" at 5993.16,1051.51 h60
  text "PTH" at 6629.72,1051.51 h60
  text "Slot" at 6888.86,1051.51 h60
  text "Top Layer - Bottom Layer" at 7264.02,1051.51 h60
  text "157 Total" at 5661.16,927.19 h60
  text "Slot definitions :" at 5360.59,840.16 h60
  text "Routed Path Length" at 5811.31,840.16 h60
  text "= Calculated from tool start centre position to tool end centre position." at 6351.05,840.16 h60
  text "Hole Length" at 5811.31,790.43 h60
  text "= Routed Path Length + Tool Size = Slot length as defined in the PCB layout" at 6151.24,790.43 h60
  text ".Layer_Name" at 577,-858.49 h60
Mechanical 17:
  text ".Layer_Name" at 577,-858.49 h60
Mechanical 18:
  text ".Layer_Name" at 577,-858.49 h60
Mechanical 19:
  text ".Layer_Name" at 577,-858.49 h60

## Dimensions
0,-400 to 1000,-400 on M2 Board Dimensions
